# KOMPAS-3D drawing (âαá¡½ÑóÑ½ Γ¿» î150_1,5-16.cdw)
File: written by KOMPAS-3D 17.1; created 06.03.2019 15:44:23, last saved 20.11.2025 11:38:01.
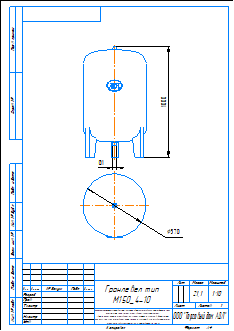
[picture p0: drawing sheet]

Sheet 1: A4, portrait

Title block, sheet 1: name: Гранлевел тип / М150_4-10; mass: 21,1; sheets: 1; sheet format: A4; stored path: C:\Users\kka\KOMPAS_Work\!Trash\ГРАНЛЕВЕЛ тип А Расширительный бак\KOMPAS 2D\Гранлевел тип А100_1,5-16.cdw

Views: Спереди 1, Спереди, Проекционный вид 2
Referenced files in C:\Users\mipv\Desktop\Тип А\SAT\: Гранлевел тип А150_4-10.a3d
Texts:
  kka
  adl
  Гранлевел тип А150_4-10
  Рама для чертежей
  Лит-Масса-Масштаб
  Материал-Предприятие
  Масштаб
  Изм.
  Лист
  № докум.
  Подп.
  Дата
  Лит.
  Разраб.
  Пров.
  Т.контр.
  Листов
  Внимание! Данный продукт является объектом авторского права ООО «Торговый Дом АДЛ».
  Запрещается изменение, копирование, распространение
  (в том числе путем копирования на другие сайты и ресурсы в Интернете)
  или любое иное использование информации и объектов без предварительного
  согласия правообладателя (ООО «Торговый Дом АДЛ»).
  Н.контр.
  Утв.
  ООО "Торговый дом АДЛ"
  Изменение
  Номер документа
  Подпись
  Обозначение документа
  Наименование изделия
  Масса изделия по ГОСТ 2.109-73
  Порядковый номер листа
  Общее количество листов в документе
  Характер работы, выполненной лицом, подписавшим документ
  Наименование или индекс предприятия, выпускающего документ
  Инв. № подл.
  Подп. и дата
  Взам. инв. №
  Инв. № дубл.
  Инвентарный номер подлинника по ГОСТ 2.501-68
  Подпись принявшего подлинник в отдел технической документации
  Инвентарный номер подлинника, взамен которого выпущен данный подлинник
  Инвентарный номер дубликата по ГОСТ 2.502-68
  Подпись принявшего дубликат в отдел технической документации
  Справ. №
  Перв. примен.
  Обозначение документа, взамен или на основании которого выпущен данный документ
  Обозначение документа, в котором впервые записан данный документ
  Подпись лица, копировавшего чертеж
  Обозначение формата листа
  !Рама для чертежа
Dimensions and other numbers on the sheet: 1000; 570; 1:10; 1; 21,1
